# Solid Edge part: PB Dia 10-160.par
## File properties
Author: Dan
Template: metric part.par
Last saved by: Dan
Revision: 3
Application: Solid Edge
Density: 7833.000 kg/m^3
Accuracy: 0.990
Material: Steel
Face Style: Steel
Fill Style: ANSI32(Steel)
Virtual Style: Machined steel
Coef. of Thermal Exp: 1.3e-05
Thermal Conductivity: 32.0
Specific Heat: 481.0
Modulus of Elasticity: 199947953000.0
Poisson's Ratio: 0.29
Yield Stress: 262000766.0
Ultimate Stress: 358527364.0
Elongation: 0.0
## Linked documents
Dia 10 - 160.par
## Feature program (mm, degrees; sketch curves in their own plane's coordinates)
part copy "CopiedPart_1"
sketch for "unnamed Cutout 1" plane through (0, 0, 0) normal (0, -1, 0) x-axis (1, 0, 0)
extrude "unnamed Cutout 1" cut through
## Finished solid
Body 1: solid body, 5 faces, 4 edges, 0 vertices.
  Faces by surface: plane 3, cylinder 2
  Edges by curve: circle 4
Bounding box of the edges (mm): 141.950 x 16.000 x 16.000, from (0, -8, -8) to (141.95, 8, 8).
Cylindrical faces by radius (mm): R5 x1, R8 x1
Planar faces by outward normal: +x 2, -x 1
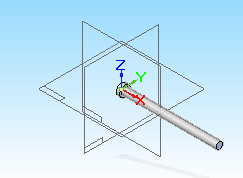
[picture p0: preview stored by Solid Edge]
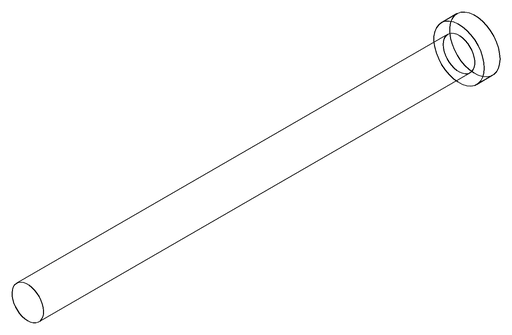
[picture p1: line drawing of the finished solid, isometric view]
